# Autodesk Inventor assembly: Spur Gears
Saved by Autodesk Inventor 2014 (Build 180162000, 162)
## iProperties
Created: 2010-12
Part Number: Spur Gears
Document SubType Name: Assembly
Designer: Thom Tremblay
Categories: <?xml version="1.0" encoding="UTF-16"?> <MemberInstance><Categories><FamilyTemplate/><ParamToTemplateMap><ParamToTemplate><ParamToTemplate CategoryParameter="//
ClientObjectVersion: 1
Author: Thom Tremblay
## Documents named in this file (1)
- C:\Inventor 2014 Essentials\Assemblies\Chapter 08\c08-01\Design Accelerator\Spur Gears5.iam
